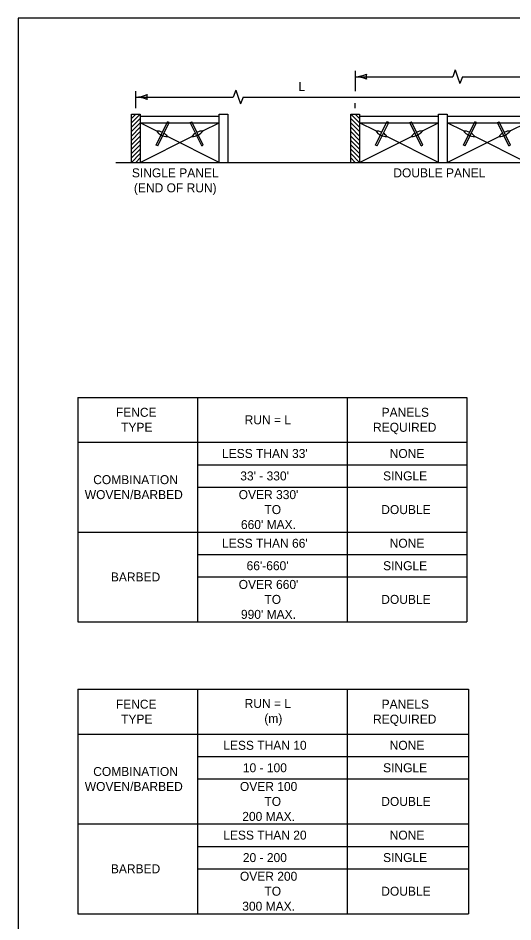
# Model space of a CAD drawing. Extents: x 49990.8 to 50021, y 49987.6 to 50011.4.
# Drawn here: x 50000.34 to 50003.64, y 50005.22 to 50011.26 of the extents above; entities that cross this region are included whole.
import ezdxf

# ---------------------------------------------------------------- set-up
doc = ezdxf.new("R2010")
doc.units = 0
for name, color, linetype in [('Level 1', 7, 'Continuous'), ('Level 2', 7, 'Continuous'), ('Level 3', 7, 'Continuous')]:
    doc.layers.add(name, color=color, linetype=linetype)

msp = doc.modelspace()

# ---------------------------------------------------------------- linework, layer by layer
at = {"layer": 'Level 1'}
for p, q in [((50001.0928, 50010.2986), (50001.0928, 50010.6214)), ((50001.0928, 50010.6214), (50001.1514, 50010.6214)), ((50001.0928, 50010.5627), (50001.1514, 50010.6214)), ((50001.0928, 50010.592), (50001.1221, 50010.6214)), ((50001.1514, 50010.6214), (50001.1514, 50010.2986)), ((50001.1514, 50010.6067), (50001.6796, 50010.6067)), ((50001.6796, 50010.2986), (50001.6796, 50010.6214)), ((50001.6796, 50010.6214), (50001.7382, 50010.6214)), ((50001.7382, 50010.6214), (50001.7382, 50010.2986)), ((50002.5598, 50010.2986), (50002.5598, 50010.6214)), ((50002.5598, 50010.6214), (50002.6184, 50010.6214)), ((50002.5598, 50010.6214), (50002.6184, 50010.5627)), ((50002.5891, 50010.6214), (50002.6184, 50010.592)), ((50002.6184, 50010.6214), (50002.6184, 50010.2986)), ((50002.6184, 50010.6067), (50003.1466, 50010.6067)), ((50003.1466, 50010.2986), (50003.1466, 50010.6214)), ((50003.1466, 50010.6214), (50003.2052, 50010.6214)), ((50003.2052, 50010.6214), (50003.2052, 50010.2986)), ((50003.2052, 50010.6067), (50003.7334, 50010.6067)), ((50001.0928, 50010.5334), (50001.1514, 50010.592)), ((50001.0928, 50010.504), (50001.1514, 50010.5627)), ((50001.1514, 50010.5627), (50001.6796, 50010.5627)), ((50001.2599, 50010.5085), (50001.1514, 50010.5627)), ((50001.2588, 50010.4146), (50001.3347, 50010.57)), ((50001.2696, 50010.4091), (50001.3462, 50010.5642)), ((50001.3462, 50010.5642), (50001.3347, 50010.57)), ((50001.4866, 50010.5642), (50001.4981, 50010.57)), ((50001.563, 50010.4091), (50001.4866, 50010.5642)), ((50001.5738, 50010.4146), (50001.4981, 50010.57)), ((50001.5717, 50010.5083), (50001.6796, 50010.5627)), ((50002.5598, 50010.592), (50002.6184, 50010.5334)), ((50002.5598, 50010.5627), (50002.6184, 50010.504)), ((50002.6184, 50010.5627), (50003.1466, 50010.5627)), ((50002.7269, 50010.5085), (50002.6184, 50010.5627)), ((50002.7258, 50010.4146), (50002.8017, 50010.57)), ((50002.7366, 50010.4091), (50002.8132, 50010.5642)), ((50002.8132, 50010.5642), (50002.8017, 50010.57)), ((50002.9536, 50010.5642), (50002.9651, 50010.57)), ((50003.03, 50010.4091), (50002.9536, 50010.5642)), ((50003.0408, 50010.4146), (50002.9651, 50010.57)), ((50003.0387, 50010.5083), (50003.1466, 50010.5627)), ((50003.2052, 50010.5627), (50003.7334, 50010.5627)), ((50003.3137, 50010.5085), (50003.2052, 50010.5627)), ((50003.3126, 50010.4146), (50003.3885, 50010.57)), ((50003.3234, 50010.4091), (50003.4, 50010.5642)), ((50003.4, 50010.5642), (50003.3885, 50010.57)), ((50003.5404, 50010.5642), (50003.5519, 50010.57)), ((50003.6168, 50010.4091), (50003.5404, 50010.5642)), ((50003.6276, 50010.4146), (50003.5519, 50010.57)), ((50003.6255, 50010.5083), (50003.7334, 50010.5627)), ((50001.0928, 50010.4747), (50001.1514, 50010.5334)), ((50001.0928, 50010.4453), (50001.1514, 50010.504)), ((50002.5598, 50010.5334), (50002.6184, 50010.4747)), ((50002.5598, 50010.504), (50002.6184, 50010.4453)), ((50001.0928, 50010.416), (50001.1514, 50010.4747)), ((50001.0928, 50010.3867), (50001.1514, 50010.4453)), ((50001.1514, 50010.2986), (50001.4981, 50010.4721)), ((50001.6796, 50010.2986), (50001.3342, 50010.4713)), ((50002.5598, 50010.4747), (50002.6184, 50010.416)), ((50002.5598, 50010.4453), (50002.6184, 50010.3867)), ((50002.6184, 50010.2986), (50002.9651, 50010.4721)), ((50003.1466, 50010.2986), (50002.8012, 50010.4713)), ((50003.2052, 50010.2986), (50003.5519, 50010.4721)), ((50003.7334, 50010.2986), (50003.388, 50010.4713)), ((50001.0928, 50010.3573), (50001.1514, 50010.416)), ((50001.0928, 50010.328), (50001.1514, 50010.3867)), ((50001.2696, 50010.4091), (50001.2588, 50010.4146)), ((50001.563, 50010.4091), (50001.5738, 50010.4146)), ((50002.5598, 50010.416), (50002.6184, 50010.3573)), ((50002.5598, 50010.3867), (50002.6184, 50010.328)), ((50002.7366, 50010.4091), (50002.7258, 50010.4146)), ((50003.03, 50010.4091), (50003.0408, 50010.4146)), ((50003.3234, 50010.4091), (50003.3126, 50010.4146)), ((50003.6168, 50010.4091), (50003.6276, 50010.4146)), ((50000.9901, 50010.2986), (50008.0023, 50010.2986)), ((50001.0928, 50010.2986), (50001.1514, 50010.3573)), ((50001.1221, 50010.2986), (50001.1514, 50010.328)), ((50002.5598, 50010.3573), (50002.6184, 50010.2986)), ((50002.5598, 50010.328), (50002.5891, 50010.2986))]:
    msp.add_line(p, q, dxfattribs=at)
msp.add_lwpolyline([(50008.6146, 50011.2628), (50000.3356, 50011.2628), (50000.3356, 50000.0624), (50008.6146, 50000.0624)], close=True, dxfattribs=at)
for centre, start, end in [((50001.3333, 50010.5623), 216.24984, 270.55889), ((50001.2616, 50010.4175), 64.77815, 91.0797), ((50001.2615, 50010.4166), 36.97154, 57.04742), ((50001.499, 50010.563), 269.43468, 323.02846), ((50001.5708, 50010.4174), 122.96631, 143.03759), ((50001.5708, 50010.4174), 89.44111, 115.05615), ((50002.8003, 50010.5623), 216.24984, 270.55889), ((50002.7286, 50010.4175), 64.77815, 91.0797), ((50002.7285, 50010.4166), 36.97154, 57.04742), ((50002.966, 50010.563), 269.43468, 323.02846), ((50003.0378, 50010.4174), 122.96631, 143.03759), ((50003.0378, 50010.4174), 89.44111, 115.05615), ((50003.3871, 50010.5623), 216.24984, 270.55889), ((50003.3154, 50010.4175), 64.77815, 91.0797), ((50003.3153, 50010.4166), 36.97154, 57.04742), ((50003.5528, 50010.563), 269.43468, 323.02846), ((50003.6246, 50010.4174), 122.96631, 143.03759), ((50003.6246, 50010.4174), 89.44111, 115.05615)]:
    msp.add_arc(centre, 0.091, start, end, dxfattribs=at)
at = {"layer": 'Level 2'}
for p, q in [((50000.7346, 50008.7287), (50003.3346, 50008.7287)), ((50000.7346, 50008.7287), (50000.7346, 50007.2287)), ((50001.5346, 50008.7287), (50001.5346, 50007.2287)), ((50002.5346, 50008.7287), (50002.5346, 50007.2287)), ((50003.3346, 50008.7287), (50003.3346, 50007.2287)), ((50000.7346, 50008.4287), (50003.3346, 50008.4287)), ((50001.5346, 50008.2787), (50003.3346, 50008.2787)), ((50001.5346, 50008.1287), (50003.3346, 50008.1287)), ((50000.7346, 50007.8287), (50003.3346, 50007.8287)), ((50001.5346, 50007.6787), (50003.3346, 50007.6787)), ((50001.5346, 50007.5287), (50003.3346, 50007.5287)), ((50000.7346, 50007.2287), (50003.3346, 50007.2287)), ((50000.7346, 50006.7787), (50003.3471, 50006.7787)), ((50000.7346, 50006.7787), (50000.7346, 50005.2787)), ((50001.5346, 50006.7787), (50001.5346, 50005.2787)), ((50002.5346, 50006.7787), (50002.5346, 50005.2787)), ((50003.3471, 50006.7787), (50003.3471, 50005.2787)), ((50000.7346, 50006.4787), (50003.3471, 50006.4787)), ((50001.5346, 50006.3287), (50003.3471, 50006.3287)), ((50001.5346, 50006.1787), (50003.3471, 50006.1787)), ((50000.7346, 50005.8787), (50003.3471, 50005.8787)), ((50001.5346, 50005.7287), (50003.3471, 50005.7287)), ((50001.5346, 50005.5787), (50003.3471, 50005.5787)), ((50000.7346, 50005.2787), (50003.3471, 50005.2787))]:
    msp.add_line(p, q, dxfattribs=at)
at = {"layer": 'Level 3'}
for p, q in [((50002.589, 50010.9108), (50002.589, 50010.7747)), ((50003.2574, 50010.9165), (50003.2412, 50010.8708)), ((50003.2574, 50010.9165), (50003.2736, 50010.8708)), ((50002.589, 50010.8708), (50003.2412, 50010.8708)), ((50003.2736, 50010.8708), (50003.2898, 50010.8251)), ((50003.306, 50010.8708), (50003.2898, 50010.8251)), ((50003.306, 50010.8708), (50005.8164, 50010.8708)), ((50001.1221, 50010.6614), (50001.1221, 50010.7747)), ((50001.1221, 50010.7347), (50001.7746, 50010.7347)), ((50001.7908, 50010.7804), (50001.7746, 50010.7347)), ((50001.7908, 50010.7804), (50001.807, 50010.7347)), ((50001.807, 50010.7347), (50001.8232, 50010.689)), ((50001.8394, 50010.7347), (50001.8232, 50010.689)), ((50001.8394, 50010.7347), (50003.7636, 50010.7347)), ((50002.5891, 50010.6614), (50002.5891, 50010.6947))]:
    msp.add_line(p, q, dxfattribs=at)
for centre, radius, start, end in [((50002.5775, 50011.1035), 0.233, 272.82731, 292.07716), ((50002.5798, 50010.6486), 0.2223, 67.45601, 87.63952), ((50002.7172, 50010.8708), 0.0548, 162.13882, 197.86118), ((50001.1106, 50010.9674), 0.233, 272.82731, 292.07716), ((50001.1129, 50010.5125), 0.2223, 67.45601, 87.63952), ((50001.2503, 50010.7347), 0.0548, 162.13882, 197.86118)]:
    msp.add_arc(centre, radius, start, end, dxfattribs=at)

# ---------------------------------------------------------------- texts
at = {"layer": 'Level 2'}
for s, p in [('L', (50002.21, 50010.7747)), ('SINGLE PANEL', (50001.0965, 50010.1986)), ('DOUBLE PANEL', (50002.8443, 50010.1986)), ('(END OF RUN)', (50001.11, 50010.0986)), ('FENCE', (50000.9894, 50008.5987)), ('RUN = L', (50001.8499, 50008.5487)), ('PANELS', (50002.7659, 50008.5987)), ('TYPE', (50001.0245, 50008.4987)), ('REQUIRED', (50002.7087, 50008.4987)), ("LESS THAN 33'", (50001.699, 50008.3237)), ('NONE', (50002.8199, 50008.3237)), ('COMBINATION', (50000.8379, 50008.1487)), ("33' - 330'", (50001.8211, 50008.1737)), ('SINGLE', (50002.7759, 50008.1737)), ('WOVEN/BARBED', (50000.7815, 50008.0487)), ("OVER 330'", (50001.8106, 50008.0487)), ('TO', (50001.9826, 50007.9487)), ('DOUBLE', (50002.7635, 50007.9487)), ("660' MAX.", (50001.8255, 50007.8487)), ("LESS THAN 66'", (50001.699, 50007.7237)), ('NONE', (50002.8199, 50007.7237)), ("66'-660'", (50001.8632, 50007.5737)), ('SINGLE', (50002.7759, 50007.5737)), ('BARBED', (50000.956, 50007.4987)), ("OVER 660'", (50001.8106, 50007.4487)), ('TO', (50001.9826, 50007.3487)), ('DOUBLE', (50002.7635, 50007.3487)), ("990' MAX.", (50001.8255, 50007.2487)), ('FENCE', (50000.9894, 50006.6487)), ('RUN = L', (50001.8499, 50006.6537)), ('PANELS', (50002.7659, 50006.6487)), ('(m)', (50001.9819, 50006.5537)), ('TYPE', (50001.0245, 50006.5487)), ('REQUIRED', (50002.7087, 50006.5487)), ('LESS THAN 10', (50001.7072, 50006.3737)), ('NONE', (50002.8199, 50006.3737)), ('COMBINATION', (50000.8379, 50006.1987)), ('10 - 100', (50001.8384, 50006.2237)), ('SINGLE', (50002.7759, 50006.2237)), ('WOVEN/BARBED', (50000.7815, 50006.0987)), ('OVER 100', (50001.8187, 50006.0987)), ('TO', (50001.9826, 50005.9987)), ('DOUBLE', (50002.7635, 50005.9987)), ('200 MAX.', (50001.8345, 50005.8987)), ('LESS THAN 20', (50001.7072, 50005.7737)), ('NONE', (50002.8199, 50005.7737)), ('20 - 200', (50001.8384, 50005.6237)), ('SINGLE', (50002.7759, 50005.6237)), ('BARBED', (50000.956, 50005.5487)), ('OVER 200', (50001.8187, 50005.4987)), ('TO', (50001.9826, 50005.3987)), ('DOUBLE', (50002.7635, 50005.3987)), ('300 MAX.', (50001.8345, 50005.2987))]:
    msp.add_text(s, height=0.06, dxfattribs=at).set_placement(p)

doc.saveas('drawing.dxf')
